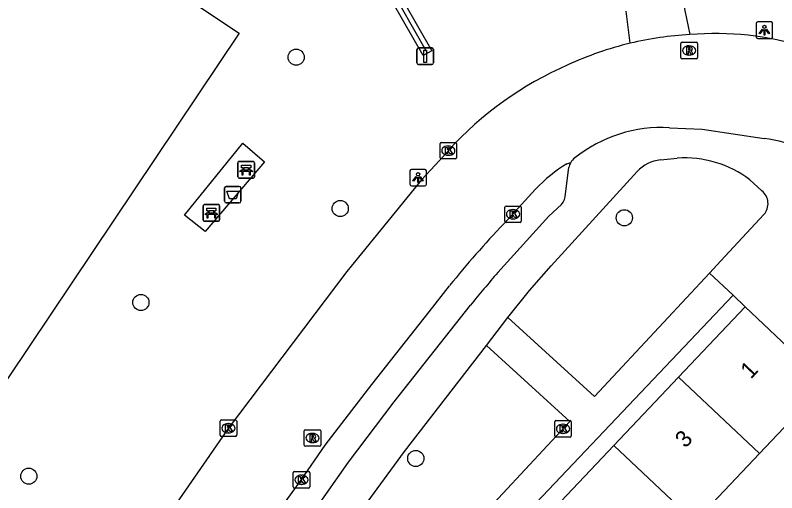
# Model space of a CAD drawing. Extents: x 159040 to 160094, y 381214 to 382518.
# Drawn here: x 159247.56 to 159293.61, y 381667.19 to 381696.1 of the extents above; entities that cross this region are included whole.
import ezdxf

# ---------------------------------------------------------------- set-up
doc = ezdxf.new("R2010")
doc.units = 0
for name, color, linetype in [('IMGEO_Afvalbak', 7, 'Continuous'), ('IMGEO_Bank', 7, 'Continuous'), ('IMGEO_Boom', 7, 'Continuous'), ('IMGEO_Fietspad_open', 7, 'Continuous'), ('IMGEO_Groenvoorziening', 7, 'Continuous'), ('IMGEO_Hek', 7, 'Continuous'), ('IMGEO_Kolk', 7, 'Continuous'), ('IMGEO_Lichtpunt', 7, 'Continuous'), ('IMGEO_Pand', 7, 'Continuous'), ('IMGEO_Pand_nummerreeks', 7, 'Continuous'), ('IMGEO_Rijbaan_lokaal_open', 7, 'Continuous'), ('IMGEO_Rioolput', 7, 'Continuous'), ('IMGEO_Verkeersbordpaal', 7, 'Continuous'), ('IMGEO_Voetpad_open', 7, 'Continuous')]:
    doc.layers.add(name, color=color, linetype=linetype)

msp = doc.modelspace()

# ---------------------------------------------------------------- linework, layer by layer
at = {"layer": 'IMGEO_Afvalbak'}
for p, q in [((159260.318, 381685.745), (159261.108, 381685.745)), ((159261.108, 381685.745), (159260.318, 381685.745)), ((159260.218, 381684.845), (159260.218, 381685.645)), ((159260.218, 381685.645), (159260.218, 381684.845)), ((159261.208, 381685.645), (159261.208, 381684.845)), ((159261.208, 381684.845), (159261.208, 381685.645)), ((159261.108, 381684.745), (159260.318, 381684.745)), ((159260.318, 381684.745), (159261.108, 381684.745))]:
    msp.add_line(p, q, dxfattribs=at)
msp.add_lwpolyline([(159260.361, 381685.459), (159261.065, 381685.459), (159260.916, 381684.989), (159260.51, 381684.989), (159260.361, 381685.459)], dxfattribs=at)
for centre, start, end in [((159260.318, 381685.645), 90, 180), ((159260.318, 381685.645), 90, 180), ((159261.108, 381685.645), 0, 90), ((159261.108, 381685.645), 360, 90), ((159260.318, 381684.845), 180, 270), ((159260.318, 381684.845), 180, 270), ((159261.108, 381684.845), 270, 0), ((159261.108, 381684.845), 270, 0)]:
    msp.add_arc(centre, 0.1, start, end, dxfattribs=at)
at = {"layer": 'IMGEO_Bank'}
for p, q in [((159261.024, 381686.321), (159261.024, 381687.162)), ((159261.024, 381687.162), (159261.024, 381686.321)), ((159261.099, 381687.246), (159261.94, 381687.246)), ((159261.94, 381687.246), (159261.099, 381687.246)), ((159262.024, 381687.171), (159262.024, 381686.33)), ((159262.024, 381686.33), (159262.024, 381687.171)), ((159261.721, 381686.644), (159261.328, 381686.644)), ((159261.333, 381686.752), (159261.333, 381686.858)), ((159261.377, 381686.858), (159261.377, 381686.752)), ((159261.665, 381686.864), (159261.383, 381686.864)), ((159261.383, 381686.746), (159261.665, 381686.746)), ((159261.671, 381686.752), (159261.671, 381686.858)), ((159261.715, 381686.858), (159261.715, 381686.752)), ((159261.949, 381686.246), (159261.108, 381686.246)), ((159261.108, 381686.246), (159261.949, 381686.246)), ((159258.918, 381683.715), (159258.918, 381684.556)), ((159258.918, 381684.556), (159258.918, 381683.715)), ((159258.993, 381684.64), (159259.834, 381684.64)), ((159259.834, 381684.64), (159258.993, 381684.64)), ((159259.918, 381684.565), (159259.918, 381683.724)), ((159259.918, 381683.724), (159259.918, 381684.565)), ((159259.615, 381684.038), (159259.222, 381684.038)), ((159259.227, 381684.146), (159259.227, 381684.252)), ((159259.271, 381684.252), (159259.271, 381684.146)), ((159259.559, 381684.258), (159259.277, 381684.258)), ((159259.277, 381684.14), (159259.559, 381684.14)), ((159259.565, 381684.146), (159259.565, 381684.252)), ((159259.609, 381684.252), (159259.609, 381684.146)), ((159259.843, 381683.64), (159259.002, 381683.64)), ((159259.002, 381683.64), (159259.843, 381683.64))]:
    msp.add_line(p, q, dxfattribs=at)
for points in [[(159261.271, 381686.644), (159261.129, 381686.644), (159261.241, 381686.746), (159261.327, 381686.746)], [(159261.327, 381686.864), (159261.241, 381686.864), (159261.241, 381687.025), (159261.804, 381687.025), (159261.804, 381686.864), (159261.721, 381686.864)], [(159261.321, 381686.637), (159261.321, 381686.43), (159261.278, 381686.43), (159261.278, 381686.637)], [(159261.721, 381686.746), (159261.804, 381686.746), (159261.916, 381686.644), (159261.777, 381686.644)], [(159261.771, 381686.637), (159261.771, 381686.43), (159261.727, 381686.43), (159261.727, 381686.637)], [(159259.221, 381684.258), (159259.135, 381684.258), (159259.135, 381684.419), (159259.698, 381684.419), (159259.698, 381684.258), (159259.615, 381684.258)], [(159259.165, 381684.038), (159259.023, 381684.038), (159259.135, 381684.14), (159259.221, 381684.14)], [(159259.215, 381684.031), (159259.215, 381683.824), (159259.172, 381683.824), (159259.172, 381684.031)], [(159259.615, 381684.14), (159259.698, 381684.14), (159259.81, 381684.038), (159259.671, 381684.038)], [(159259.665, 381684.031), (159259.665, 381683.824), (159259.621, 381683.824), (159259.621, 381684.031)]]:
    msp.add_lwpolyline(points, dxfattribs=at)
for centre, radius, start, end in [((159261.102, 381687.168), 0.0779, 92.4484, 184.2845), ((159261.102, 381687.168), 0.0779, 92.4484, 184.2845), ((159261.946, 381687.168), 0.0779, 2.4484, 94.2845), ((159261.946, 381687.168), 0.0779, 2.4484, 94.2845), ((159261.271, 381686.637), 0.00671, 2.8957, 87.1043), ((159261.328, 381686.637), 0.00671, 92.8957, 177.1043), ((159261.326, 381686.857), 0.00671, 2.8957, 87.1043), ((159261.326, 381686.753), 0.00671, 272.8957, 357.1043), ((159261.383, 381686.857), 0.00671, 92.8957, 177.1043), ((159261.383, 381686.753), 0.00671, 182.8957, 267.1043), ((159261.665, 381686.857), 0.00671, 2.8957, 87.1043), ((159261.665, 381686.753), 0.00671, 272.8957, 357.1043), ((159261.722, 381686.857), 0.00671, 92.8957, 177.1043), ((159261.722, 381686.753), 0.00671, 182.8957, 267.1043), ((159261.72, 381686.637), 0.00671, 2.8957, 87.1043), ((159261.777, 381686.637), 0.00671, 92.8957, 177.1043), ((159261.102, 381686.324), 0.0779, 182.4484, 274.2845), ((159261.102, 381686.324), 0.0779, 182.4484, 274.2845), ((159261.946, 381686.324), 0.0779, 272.4484, 4.2845), ((159261.946, 381686.324), 0.0779, 272.4484, 4.2845), ((159258.996, 381684.562), 0.0779, 92.4484, 184.2845), ((159258.996, 381684.562), 0.0779, 92.4484, 184.2845), ((159259.84, 381684.562), 0.0779, 2.4484, 94.2845), ((159259.84, 381684.562), 0.0779, 2.4484, 94.2845), ((159259.165, 381684.031), 0.00671, 2.8957, 87.1043), ((159259.222, 381684.031), 0.00671, 92.8957, 177.1043), ((159259.22, 381684.251), 0.00671, 2.8957, 87.1043), ((159259.22, 381684.147), 0.00671, 272.8957, 357.1043), ((159259.277, 381684.251), 0.00671, 92.8957, 177.1043), ((159259.277, 381684.147), 0.00671, 182.8957, 267.1043), ((159259.559, 381684.251), 0.00671, 2.8957, 87.1043), ((159259.559, 381684.147), 0.00671, 272.8957, 357.1043), ((159259.616, 381684.251), 0.00671, 92.8957, 177.1043), ((159259.616, 381684.147), 0.00671, 182.8957, 267.1043), ((159259.614, 381684.031), 0.00671, 2.8957, 87.1043), ((159259.671, 381684.031), 0.00671, 92.8957, 177.1043), ((159258.996, 381683.718), 0.0779, 182.4484, 274.2845), ((159258.996, 381683.718), 0.0779, 182.4484, 274.2845), ((159259.84, 381683.718), 0.0779, 272.4484, 4.2845), ((159259.84, 381683.718), 0.0779, 272.4484, 4.2845)]:
    msp.add_arc(centre, radius, start, end, dxfattribs=at)
at = {"layer": 'IMGEO_Boom'}
for centre in [(159264.546, 381693.562), (159267.211, 381684.401), (159284.39, 381683.842), (159255.157, 381678.715), (159271.778, 381669.273), (159248.379, 381668.199)]:
    msp.add_circle(centre, 0.489, dxfattribs=at)
at = {"layer": 'IMGEO_Fietspad_open'}
for points in [[(159287.955, 381696.867), (159288.347, 381694.934)], [(159284.739, 381694.404), (159284.508, 381696.345)]]:
    msp.add_lwpolyline(points, dxfattribs=at)
at = {"layer": 'IMGEO_Groenvoorziening'}
for points in [[(159243.856, 381715.767), (159244.071, 381716.327), (159260.635, 381709.968), (159262.836, 381708.616), (159264.619, 381706.785), (159266.156, 381704.742), (159270.235, 381698.359), (159272.745, 381693.954), (159272.224, 381693.657), (159269.721, 381698.049), (159265.662, 381704.4), (159264.163, 381706.393), (159262.458, 381708.144), (159260.369, 381709.428), (159243.856, 381715.767)], [(159243.346, 381668.514), (159222.578, 381682.432), (159240.298, 381708.872), (159261.103, 381695.01), (159243.346, 381668.514)]]:
    msp.add_lwpolyline(points, dxfattribs=at)
at = {"layer": 'IMGEO_Hek'}
msp.add_lwpolyline([(159243.986, 381716.038), (159260.502, 381709.698), (159262.647, 381708.38), (159264.391, 381706.589), (159265.909, 381704.571), (159269.978, 381698.204), (159272.474, 381693.824)], dxfattribs=at)
at = {"layer": 'IMGEO_Kolk'}
for p, q in [((159273.247, 381687.478), (159273.247, 381688.33)), ((159273.322, 381688.404), (159274.174, 381688.404)), ((159273.735, 381688.184), (159273.76, 381688.184)), ((159274.248, 381688.33), (159274.248, 381687.478)), ((159273.758, 381687.624), (159273.733, 381687.624)), ((159274.174, 381687.404), (159273.322, 381687.404)), ((159277.159, 381683.628), (159277.159, 381684.48)), ((159277.234, 381684.554), (159278.086, 381684.554)), ((159277.647, 381684.334), (159277.672, 381684.334)), ((159278.16, 381684.48), (159278.16, 381683.628)), ((159278.086, 381683.554), (159277.234, 381683.554)), ((159277.67, 381683.774), (159277.645, 381683.774)), ((159259.949, 381670.675), (159259.949, 381671.527)), ((159260.024, 381671.601), (159260.876, 381671.601)), ((159260.95, 381671.527), (159260.95, 381670.675)), ((159280.182, 381670.639), (159280.182, 381671.491)), ((159280.257, 381671.565), (159281.109, 381671.565)), ((159281.183, 381671.491), (159281.183, 381670.639)), ((159260.437, 381671.381), (159260.462, 381671.381)), ((159280.67, 381671.345), (159280.695, 381671.345)), ((159260.876, 381670.601), (159260.024, 381670.601)), ((159260.46, 381670.821), (159260.435, 381670.821)), ((159281.109, 381670.565), (159280.257, 381670.565)), ((159280.693, 381670.785), (159280.668, 381670.785)), ((159264.367, 381667.557), (159264.367, 381668.409)), ((159264.442, 381668.483), (159265.294, 381668.483)), ((159264.855, 381668.263), (159264.88, 381668.263)), ((159265.368, 381668.409), (159265.368, 381667.557)), ((159265.294, 381667.483), (159264.442, 381667.483)), ((159264.878, 381667.703), (159264.853, 381667.703))]:
    msp.add_line(p, q, dxfattribs=at)
for points in [[(159273.247, 381687.478), (159273.247, 381688.33)], [(159273.322, 381688.404), (159274.174, 381688.404)], [(159273.568, 381688.104), (159273.691, 381688.104), (159273.691, 381687.953), (159273.821, 381688.104), (159273.985, 381688.104), (159273.839, 381687.953), (159273.992, 381687.704), (159273.84, 381687.704), (159273.755, 381687.868), (159273.691, 381687.801), (159273.691, 381687.704), (159273.568, 381687.704), (159273.568, 381688.104)], [(159274.248, 381688.33), (159274.248, 381687.478)], [(159274.174, 381687.404), (159273.322, 381687.404)], [(159277.159, 381683.628), (159277.159, 381684.48)], [(159277.234, 381684.554), (159278.086, 381684.554)], [(159278.16, 381684.48), (159278.16, 381683.628)], [(159277.48, 381684.254), (159277.603, 381684.254), (159277.603, 381684.103), (159277.733, 381684.254), (159277.897, 381684.254), (159277.751, 381684.103), (159277.904, 381683.854), (159277.752, 381683.854), (159277.667, 381684.018), (159277.603, 381683.951), (159277.603, 381683.854), (159277.48, 381683.854), (159277.48, 381684.254)], [(159278.086, 381683.554), (159277.234, 381683.554)], [(159259.949, 381670.675), (159259.949, 381671.527)], [(159260.024, 381671.601), (159260.876, 381671.601)], [(159260.95, 381671.527), (159260.95, 381670.675)], [(159280.182, 381670.639), (159280.182, 381671.491)], [(159280.257, 381671.565), (159281.109, 381671.565)], [(159281.183, 381671.491), (159281.183, 381670.639)], [(159260.27, 381671.301), (159260.393, 381671.301), (159260.393, 381671.15), (159260.523, 381671.301), (159260.687, 381671.301), (159260.541, 381671.15), (159260.694, 381670.901), (159260.542, 381670.901), (159260.457, 381671.065), (159260.393, 381670.998), (159260.393, 381670.901), (159260.27, 381670.901), (159260.27, 381671.301)], [(159280.503, 381671.265), (159280.626, 381671.265), (159280.626, 381671.114), (159280.756, 381671.265), (159280.92, 381671.265), (159280.774, 381671.114), (159280.927, 381670.865), (159280.775, 381670.865), (159280.69, 381671.029), (159280.626, 381670.962), (159280.626, 381670.865), (159280.503, 381670.865), (159280.503, 381671.265)], [(159260.876, 381670.601), (159260.024, 381670.601)], [(159281.109, 381670.565), (159280.257, 381670.565)], [(159264.367, 381667.557), (159264.367, 381668.409)], [(159264.442, 381668.483), (159265.294, 381668.483)], [(159264.688, 381668.183), (159264.811, 381668.183), (159264.811, 381668.032), (159264.941, 381668.183), (159265.105, 381668.183), (159264.959, 381668.032), (159265.112, 381667.783), (159264.96, 381667.783), (159264.875, 381667.947), (159264.811, 381667.88), (159264.811, 381667.783), (159264.688, 381667.783), (159264.688, 381668.183)], [(159265.368, 381668.409), (159265.368, 381667.557)], [(159265.294, 381667.483), (159264.442, 381667.483)]]:
    msp.add_lwpolyline(points, dxfattribs=at)
for centre, start, end in [((159273.324, 381688.328), 91.552, 178.448), ((159273.324, 381688.328), 91.552, 178.448), ((159274.172, 381688.328), 1.552, 88.448), ((159274.172, 381688.328), 1.552, 88.448), ((159273.324, 381687.48), 181.552, 268.448), ((159273.324, 381687.48), 181.552, 268.448), ((159274.172, 381687.48), 271.552, 358.448), ((159274.172, 381687.48), 271.552, 358.448), ((159277.236, 381684.478), 91.552, 178.448), ((159277.236, 381684.478), 91.552, 178.448), ((159278.084, 381684.478), 1.552, 88.448), ((159278.084, 381684.478), 1.552, 88.448), ((159277.236, 381683.63), 181.552, 268.448), ((159277.236, 381683.63), 181.552, 268.448), ((159278.084, 381683.63), 271.552, 358.448), ((159278.084, 381683.63), 271.552, 358.448), ((159260.026, 381671.525), 91.552, 178.448), ((159260.026, 381671.525), 91.552, 178.448), ((159260.874, 381671.525), 1.552, 88.448), ((159260.874, 381671.525), 1.552, 88.448), ((159280.259, 381671.489), 91.552, 178.448), ((159280.259, 381671.489), 91.552, 178.448), ((159281.107, 381671.489), 1.552, 88.448), ((159281.107, 381671.489), 1.552, 88.448), ((159260.026, 381670.677), 181.552, 268.448), ((159260.026, 381670.677), 181.552, 268.448), ((159260.874, 381670.677), 271.552, 358.448), ((159260.874, 381670.677), 271.552, 358.448), ((159280.259, 381670.641), 181.552, 268.448), ((159280.259, 381670.641), 181.552, 268.448), ((159281.107, 381670.641), 271.552, 358.448), ((159281.107, 381670.641), 271.552, 358.448), ((159264.444, 381668.407), 91.552, 178.448), ((159264.444, 381668.407), 91.552, 178.448), ((159265.292, 381668.407), 1.552, 88.448), ((159265.292, 381668.407), 1.552, 88.448), ((159264.444, 381667.559), 181.552, 268.448), ((159264.444, 381667.559), 181.552, 268.448), ((159265.292, 381667.559), 271.552, 358.448), ((159265.292, 381667.559), 271.552, 358.448)]:
    msp.add_arc(centre, 0.0765, start, end, dxfattribs=at)
for centre, major_axis, ratio, start_param, end_param in [((159273.734, 381687.904), (-0.387, 0.002), 0.722429, 4.712389, 7.853982), ((159273.759, 381687.904), (-0.39, 0.002), 0.717154, 1.570796, 4.712389), ((159277.646, 381684.054), (-0.387, 0.002), 0.722429, 4.712389, 7.853982), ((159277.671, 381684.054), (-0.39, 0.002), 0.717154, 1.570796, 4.712389), ((159260.436, 381671.101), (-0.387, 0.002), 0.722429, 4.712389, 7.853982), ((159260.461, 381671.101), (-0.39, 0.002), 0.717154, 1.570796, 4.712389), ((159280.669, 381671.065), (-0.387, 0.002), 0.722429, 4.712389, 7.853982), ((159280.694, 381671.065), (-0.39, 0.002), 0.717154, 1.570796, 4.712389), ((159264.854, 381667.983), (-0.387, 0.002), 0.722429, 4.712389, 7.853982), ((159264.879, 381667.983), (-0.39, 0.002), 0.717154, 1.570796, 4.712389)]:
    msp.add_ellipse(centre, major_axis=major_axis, ratio=ratio, start_param=start_param, end_param=end_param, dxfattribs=at)
at = {"layer": 'IMGEO_Lichtpunt'}
for p, q in [((159292.362, 381695.602), (159292.362, 381694.795)), ((159292.362, 381695.602), (159292.362, 381694.795)), ((159293.264, 381695.697), (159292.456, 381695.697)), ((159293.264, 381695.697), (159292.456, 381695.697)), ((159293.358, 381694.795), (159293.358, 381695.602)), ((159293.358, 381694.795), (159293.358, 381695.602)), ((159292.456, 381694.701), (159293.264, 381694.701)), ((159292.456, 381694.701), (159293.264, 381694.701)), ((159271.423, 381686.675), (159271.423, 381685.868)), ((159271.423, 381686.675), (159271.423, 381685.868)), ((159272.325, 381686.77), (159271.517, 381686.77)), ((159272.325, 381686.77), (159271.517, 381686.77)), ((159272.419, 381685.868), (159272.419, 381686.675)), ((159272.419, 381685.868), (159272.419, 381686.675)), ((159271.517, 381685.774), (159272.325, 381685.774)), ((159271.517, 381685.774), (159272.325, 381685.774))]:
    msp.add_line(p, q, dxfattribs=at)
for points in [[(159292.736, 381695.266), (159292.775, 381695.238), (159292.587, 381694.976), (159292.549, 381695.003), (159292.736, 381695.266)], [(159292.838, 381695.218), (159292.885, 381695.218), (159292.885, 381694.896), (159292.838, 381694.896), (159292.838, 381695.218)], [(159292.948, 381695.238), (159292.986, 381695.265), (159293.173, 381695.003), (159293.134, 381694.975), (159292.948, 381695.238)], [(159271.797, 381686.339), (159271.836, 381686.311), (159271.648, 381686.049), (159271.61, 381686.076), (159271.797, 381686.339)], [(159271.899, 381686.291), (159271.946, 381686.291), (159271.946, 381685.969), (159271.899, 381685.969), (159271.899, 381686.291)], [(159272.009, 381686.311), (159272.047, 381686.338), (159272.234, 381686.076), (159272.195, 381686.048), (159272.009, 381686.311)]]:
    msp.add_lwpolyline(points, dxfattribs=at)
for centre in [(159292.861, 381695.4), (159271.922, 381686.473)]:
    msp.add_circle(centre, 0.0994, dxfattribs=at)
for centre, start, end in [((159292.456, 381695.602), 90, 180), ((159292.456, 381695.602), 90, 180), ((159293.264, 381695.602), 0, 90), ((159293.264, 381695.602), 0, 90), ((159292.456, 381694.795), 180, 270), ((159292.456, 381694.795), 180, 270), ((159293.264, 381694.795), 270, 0), ((159293.264, 381694.795), 270, 360), ((159271.517, 381686.675), 90, 180), ((159271.517, 381686.675), 90, 180), ((159272.325, 381686.675), 0, 90), ((159272.325, 381686.675), 0, 90), ((159271.517, 381685.868), 180, 270), ((159271.517, 381685.868), 180, 270), ((159272.325, 381685.868), 270, 0), ((159272.325, 381685.868), 270, 360)]:
    msp.add_arc(centre, 0.0946, start, end, dxfattribs=at)
at = {"layer": 'IMGEO_Pand'}
for points in [[(159291.702, 381678.458), (159287.668, 381674.195)], [(159291.702, 381678.458), (159295.025, 381675.313)], [(159295.025, 381675.313), (159296.595, 381673.828), (159292.562, 381669.565)], [(159287.668, 381674.195), (159283.762, 381670.065)], [(159287.668, 381674.195), (159292.562, 381669.565)], [(159283.762, 381670.065), (159279.836, 381665.917)], [(159283.762, 381670.065), (159288.655, 381665.436)], [(159292.562, 381669.565), (159288.655, 381665.436)]]:
    msp.add_lwpolyline(points, dxfattribs=at)
at = {"layer": 'IMGEO_Rijbaan_lokaal_open'}
for points in [[(159287.128, 381689.292), (159289.1, 381689.201), (159292.84, 381688.646)], [(159273.747, 381687.9), (159272.115, 381686.142), (159267.603, 381680.595), (159260.442, 381671.089), (159255.999, 381664.677)], [(159280.919, 381687.114), (159281.15, 381687.184)], [(159277.094, 381683.471), (159279.017, 381685.573)], [(159260.413, 381661.709), (159261.276, 381663.007), (159264.834, 381667.935), (159266.302, 381670.07), (159269.115, 381673.75), (159272.579, 381678.156), (159273.822, 381679.732)]]:
    msp.add_lwpolyline(points, dxfattribs=at)
for centre, radius, start, end in [((159289.468, 381674.758), 20.207, 93.1796, 103.5339), ((159289.866, 381676.584), 18.413, 50.8897, 94.7314), ((159289.495, 381674.643), 20.326, 103.532, 114.7918), ((159289.371, 381673.792), 21.051, 113.5149, 137.9198), ((159286.658, 381680.862), 8.443, 86.8083, 128.5621), ((159290.979, 381676.253), 12.532, 58.8769, 81.462), ((159285.546, 381679.459), 8.944, 121.1494, 136.8794), ((159281.987, 381686.699), 0.967, 127.7229, 149.9053), ((159318.344, 381644.072), 57.043, 136.3148, 141.3069)]:
    msp.add_arc(centre, radius, start, end, dxfattribs=at)
at = {"layer": 'IMGEO_Rioolput'}
for p, q in [((159287.881, 381694.47), (159288.733, 381694.47)), ((159287.806, 381693.544), (159287.806, 381694.396)), ((159288.294, 381694.25), (159288.319, 381694.25)), ((159288.807, 381694.396), (159288.807, 381693.544)), ((159288.317, 381693.69), (159288.292, 381693.69)), ((159288.733, 381693.47), (159287.881, 381693.47)), ((159265.105, 381671.011), (159265.957, 381671.011)), ((159265.03, 381670.085), (159265.03, 381670.937)), ((159265.518, 381670.791), (159265.543, 381670.791)), ((159266.031, 381670.937), (159266.031, 381670.085)), ((159265.541, 381670.231), (159265.516, 381670.231)), ((159265.957, 381670.011), (159265.105, 381670.011))]:
    msp.add_line(p, q, dxfattribs=at)
for points in [[(159287.881, 381694.47), (159288.733, 381694.47)], [(159287.806, 381693.544), (159287.806, 381694.396)], [(159288.395, 381694.168), (159288.143, 381694.17), (159288.143, 381693.77)], [(159288.321, 381694.089), (159288.267, 381694.089), (159288.267, 381694.008)], [(159288.267, 381694.008), (159288.319, 381694.008)], [(159288.807, 381694.396), (159288.807, 381693.544)], [(159288.143, 381693.77), (159288.267, 381693.77), (159288.267, 381693.932), (159288.278, 381693.932)], [(159288.325, 381693.903), (159288.396, 381693.77), (159288.536, 381693.77), (159288.471, 381693.896)], [(159288.733, 381693.47), (159287.881, 381693.47)], [(159265.105, 381671.011), (159265.957, 381671.011)], [(159265.03, 381670.085), (159265.03, 381670.937)], [(159265.619, 381670.709), (159265.367, 381670.711), (159265.367, 381670.311)], [(159265.545, 381670.63), (159265.491, 381670.63), (159265.491, 381670.549)], [(159265.491, 381670.549), (159265.543, 381670.549)], [(159266.031, 381670.937), (159266.031, 381670.085)], [(159265.367, 381670.311), (159265.491, 381670.311), (159265.491, 381670.473), (159265.502, 381670.473)], [(159265.549, 381670.444), (159265.62, 381670.311), (159265.76, 381670.311), (159265.695, 381670.437)], [(159265.957, 381670.011), (159265.105, 381670.011)]]:
    msp.add_lwpolyline(points, dxfattribs=at)
for centre, radius, start, end in [((159287.883, 381694.394), 0.0765, 91.552, 178.448), ((159287.883, 381694.394), 0.0765, 91.552, 178.448), ((159288.731, 381694.394), 0.0765, 1.552, 88.448), ((159288.731, 381694.394), 0.0765, 1.552, 88.448), ((159288.303, 381694.197), 0.19, 274.7715, 282.9687), ((159288.327, 381693.993), 0.0964, 77.0061, 93.1865), ((159288.341, 381694.05), 0.0378, 276.6634, 79.6772), ((159288.394, 381694.058), 0.109, 350.3612, 89.416), ((159288.392, 381694.058), 0.112, 277.5842, 350.9817), ((159287.883, 381693.546), 0.0765, 181.552, 268.448), ((159287.883, 381693.546), 0.0765, 181.552, 268.448), ((159288.277, 381693.879), 0.0533, 26.0293, 88.6989), ((159288.376, 381693.843), 0.108, 29.5134, 73.7905), ((159288.731, 381693.546), 0.0765, 271.552, 358.448), ((159288.731, 381693.546), 0.0765, 271.552, 358.448), ((159265.107, 381670.935), 0.0765, 91.552, 178.448), ((159265.107, 381670.935), 0.0765, 91.552, 178.448), ((159265.955, 381670.935), 0.0765, 1.552, 88.448), ((159265.955, 381670.935), 0.0765, 1.552, 88.448), ((159265.527, 381670.738), 0.19, 274.7715, 282.9687), ((159265.551, 381670.534), 0.0964, 77.0061, 93.1865), ((159265.565, 381670.591), 0.0378, 276.6634, 79.6772), ((159265.618, 381670.599), 0.109, 350.3612, 89.416), ((159265.616, 381670.599), 0.112, 277.5842, 350.9817), ((159265.6, 381670.384), 0.108, 29.5134, 73.7905), ((159265.107, 381670.087), 0.0765, 181.552, 268.448), ((159265.107, 381670.087), 0.0765, 181.552, 268.448), ((159265.501, 381670.42), 0.0533, 26.0293, 88.6989), ((159265.955, 381670.087), 0.0765, 271.552, 358.448), ((159265.955, 381670.087), 0.0765, 271.552, 358.448)]:
    msp.add_arc(centre, radius, start, end, dxfattribs=at)
for centre, major_axis, ratio, start_param, end_param in [((159288.293, 381693.97), (-0.387, 0.002), 0.722429, 4.712389, 7.853982), ((159288.318, 381693.97), (-0.39, 0.002), 0.717154, 1.570796, 4.712389), ((159265.517, 381670.511), (-0.387, 0.002), 0.722429, 4.712389, 7.853982), ((159265.542, 381670.511), (-0.39, 0.002), 0.717154, 1.570796, 4.712389)]:
    msp.add_ellipse(centre, major_axis=major_axis, ratio=ratio, start_param=start_param, end_param=end_param, dxfattribs=at)
at = {"layer": 'IMGEO_Verkeersbordpaal'}
for p, q in [((159271.851, 381693.22), (159271.851, 381694.02)), ((159271.851, 381694.02), (159271.851, 381693.22)), ((159271.951, 381694.12), (159272.741, 381694.12)), ((159272.741, 381694.12), (159271.951, 381694.12)), ((159272.841, 381694.02), (159272.841, 381693.22)), ((159272.841, 381693.22), (159272.841, 381694.02)), ((159272.741, 381693.12), (159271.951, 381693.12)), ((159271.951, 381693.12), (159272.741, 381693.12))]:
    msp.add_line(p, q, dxfattribs=at)
msp.add_lwpolyline([(159272.271, 381693.995), (159272.421, 381693.995), (159272.421, 381693.245), (159272.271, 381693.245), (159272.271, 381693.995)], dxfattribs=at)
for centre, start, end in [((159271.951, 381694.02), 90, 180), ((159271.951, 381694.02), 90, 180), ((159272.741, 381694.02), 0, 90), ((159272.741, 381694.02), 360, 90), ((159271.951, 381693.22), 180, 270), ((159271.951, 381693.22), 180, 270), ((159272.741, 381693.22), 270, 0), ((159272.741, 381693.22), 270, 0)]:
    msp.add_arc(centre, 0.1, start, end, dxfattribs=at)
at = {"layer": 'IMGEO_Voetpad_open'}
for points in [[(159259.037, 381683.005), (159257.801, 381684.006), (159261.318, 381688.349), (159262.631, 381687.233), (159259.037, 381683.005)], [(159286.574, 381687.347), (159287.591, 381687.447)], [(159277.344, 381677.805), (159278.648, 381679.447), (159279.968, 381680.942), (159285.159, 381686.638)], [(159280.827, 381685.293), (159281.036, 381686.889)], [(159291.984, 381686.14), (159292.71, 381685.478)], [(159276.737, 381680.521), (159279.832, 381683.934), (159280.588, 381684.641)], [(159292.832, 381684.031), (159290.223, 381681.231), (159289.531, 381680.488)], [(159289.531, 381680.488), (159282.581, 381673.027), (159277.344, 381677.805)], [(159289.531, 381680.488), (159290.97, 381679.148)], [(159263.796, 381650.493), (159290.97, 381679.148)], [(159290.97, 381679.148), (159291.702, 381678.458)], [(159252.698, 381646.729), (159254.866, 381650.157), (159257.501, 381654.264), (159260.388, 381658.551), (159262.696, 381662.023), (159266.246, 381666.94), (159267.701, 381669.055), (159270.48, 381672.691), (159275.088, 381678.55)], [(159276.049, 381676.12), (159277.344, 381677.805)], [(159267.635, 381664.961), (159271.102, 381669.693), (159276.049, 381676.12)], [(159267.635, 381664.961), (159271.637, 381661.344), (159281.099, 381671.509), (159276.049, 381676.12)]]:
    msp.add_lwpolyline(points, dxfattribs=at)
for centre, radius, start, end in [((159281.997, 381686.687), 0.982, 149.6048, 168.138), ((159286.794, 381685.141), 2.217, 95.7049, 137.5224), ((159288.069, 381681.019), 6.446, 52.6065, 94.256), ((159279.75, 381685.318), 1.077, 321.0623, 358.6754), ((159292.059, 381684.694), 1.019, 319.3722, 50.2664), ((159318.354, 381644.028), 55.351, 138.7529, 141.4133)]:
    msp.add_arc(centre, radius, start, end, dxfattribs=at)

# ---------------------------------------------------------------- texts
at = {"layer": 'IMGEO_Pand_nummerreeks'}
for s, p in [('1', (159292.035, 381674.037)), ('3', (159288.08, 381669.856))]:
    msp.add_text(s, height=1, rotation=46.5863, dxfattribs=at).set_placement(p)

doc.saveas('drawing.dxf')
